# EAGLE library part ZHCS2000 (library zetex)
SHOTTKY DIODE
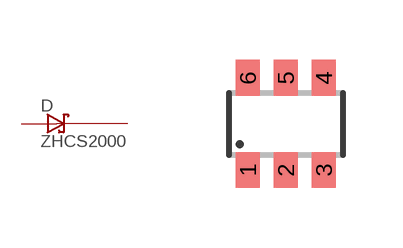
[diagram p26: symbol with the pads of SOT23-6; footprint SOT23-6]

Designator prefix D

## ZHCS2000 (MPN: ZHCS2000; OC_FARNELL: 9525653; OC_NEWARK: 98K3992)  [SOT23-6]
1  C  pas
2  C1  pas
3  A  pas
4  A1  pas
5  C2  pas
6  C3  pas

## Footprint SOT23-6 (pad centres in mm)
Small Outline Transistor 6 lead
smd 0.6 x 0.9: 1 -0.95,-1.15; 2 0,-1.15; 3 0.95,-1.15; 4 0.95,1.15; 5 0,1.15; 6 -0.95,1.15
